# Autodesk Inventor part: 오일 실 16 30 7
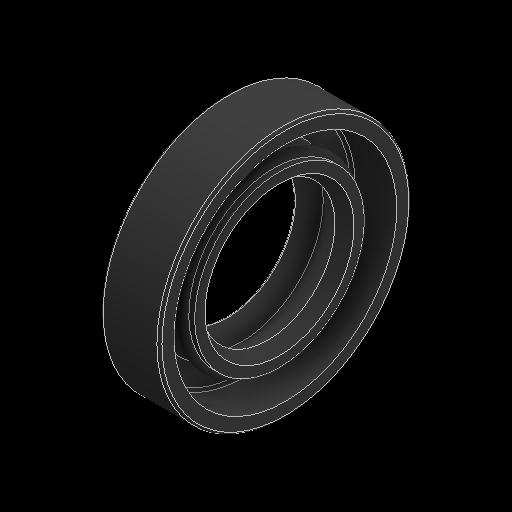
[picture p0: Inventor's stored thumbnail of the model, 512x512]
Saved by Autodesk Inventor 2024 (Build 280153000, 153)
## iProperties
Created: 2025-10
Part Number: 오일 실 16 30 7
Material: 고무
Description: 오일-실
Document SubType Name: Modeling
Designer: EDU03
Density: 0.93 g/cm^3
Appearance: 기본값
Author: jhkim
Sending System: Autodesk Inventor 2026
Preprocessor: ST-DEVELOPER v20.1
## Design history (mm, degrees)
node "오일 실 16 30 71"
node "솔리드1"
body "Solid1"
